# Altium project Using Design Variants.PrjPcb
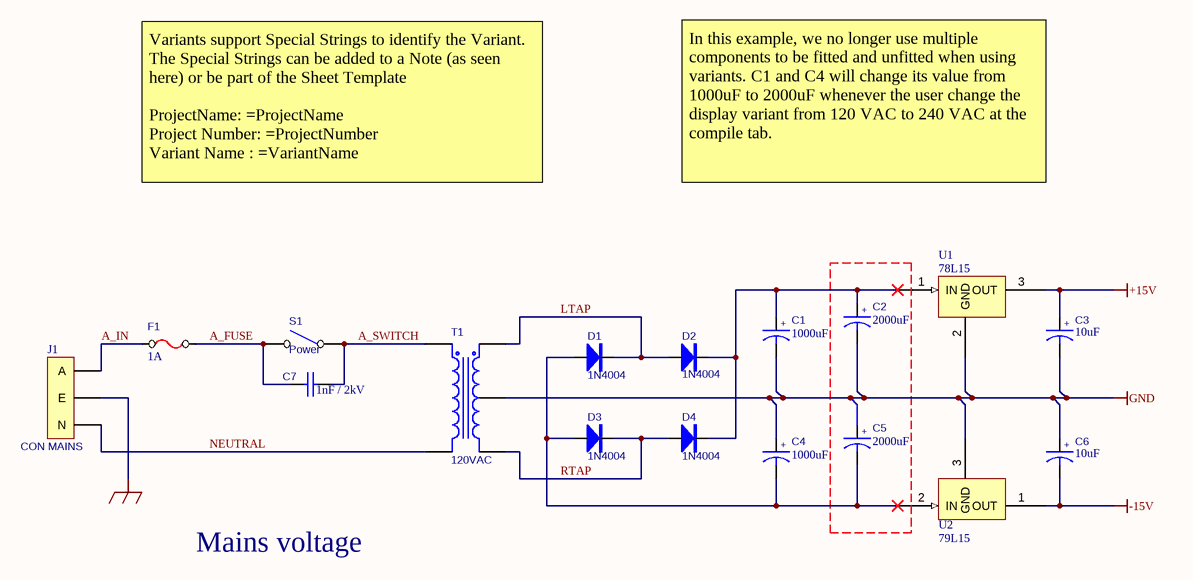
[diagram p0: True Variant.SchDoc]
ProjectNumber: ABC123-Default
1 sheet, 17 parts. Net scope: global (net labels, ports and power ports of the same name join across sheets).
Board file: True Variant.PcbDoc

## Sheet True Variant.SchDoc: Using Design Variants
size 431 x 279 mm; SheetNumber: 1; SheetTotal: 1

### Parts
C1  1000uF  [RB.4/.8]
C2  2000uF  [RB.5/1.0]
C3  10uF  [RB.2/.4]
C4  1000uF  [RB.4/.8]
C5  2000uF  [RB.5/1.0]
C6  10uF  [RB.2/.4]
C7  1nF / 2kV  [RAD0.8]
D1  1N4004  [DIODE0.5]
D2  1N4004  [DIODE0.5]
D3  1N4004  [DIODE0.5]
D4  1N4004  [DIODE0.5]
F1  1A  [FUSE]
J1  CON MAINS  [IEC-MAINS]
S1  Power  [SW-MAINS]
T1  120VAC  [TRANSFORMER]
U1  78L15  [TO-92A]
U2  79L15  [TO-92A]

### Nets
+15V: C3.1 U1.3(OUT)
-15V: C6.2 U2.1(OUT)
CHASSIS: J1.2(E)
GND: C1.2 C2.2 C3.2 C4.1 C5.1 C6.1 T1.4(SecCT) U1.2(GND) U2.3(GND)
A_FUSE: C7.2 F1.2 S1.2(NO)
A_IN: F1.1 J1.1(A)
A_SWITCH: C7.1 S1.1(COMMON) T1.1(Pri+)
LTAP: D1.2(K) D2.1(A) T1.3(Sec+)
NEUTRAL: J1.3(N) T1.2(Pri-)
RTAP: D3.2(K) D4.1(A) T1.5(Sec-)
NetC1_1: C1.1 C2.1 D2.2(K) D4.2(K) U1.1(IN)
NetC4_2: C4.2 C5.2 D1.1(A) D3.1(A) U2.2(IN)

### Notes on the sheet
- Variants support Special Strings to identify the Variant.
  The Special Strings can be added to a Note (as seen here) or be part of the Sheet Template
  ProjectName: =ProjectName
  Project Number: =ProjectNumber
  Variant Name : =VariantName
- In this example, we no longer use multiple components to be fitted and unfitted when using variants. C1 and C4 will change its value from 1000uF to 2000uF whenever the user change the display variant from 120 VAC to 240 VAC at the compile tab.
- Mains voltage

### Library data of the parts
C1 C4 = CAP1000uF: Bi-Polar Capacitor
C2 C5 = CAPACITOR POL2: Bi-Polar Capacitor
C3 C6 = CAPACITOR POL: Bi-Polar Capacitor
C7 = CAP: Capacitor
D1-D4 = 1N4004: Diode
F1 = FUSE
J1 = CON MAINS: Connector
S1 = SW SPST
T1 = 120VAC: Center-Tapped Transformer
U1 = 78L15: Very Low Drop Voltage Regulators With Inhibit
U2 = 79L15: Very Low Drop Voltage Regulators With Inhibit

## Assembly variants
120VAC: not fitted C2 C5
240VAC: not fitted C1 C4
